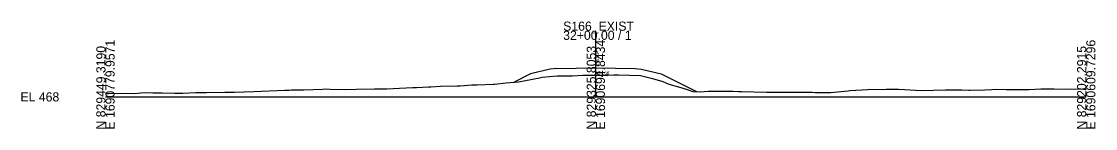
# Model space of a CAD drawing. Extents: x 1621104 to 1621433, y 1192880 to 1199414.
# Drawn here: x 1621104.2 to 1621432.7, y 1197379.5 to 1197412.3 of the extents above; entities that cross this region are included whole.
import ezdxf

# ---------------------------------------------------------------- set-up
doc = ezdxf.new("R2010")
doc.units = 0
for name, color, linetype in [('RD_GPK_XS_Cell', 7, 'Continuous'), ('RD_XS_EarthShd', 7, 'Continuous'), ('RD_XS_ExGround', 7, 'Continuous'), ('RD_XS_Pave', 7, 'Continuous'), ('RD_XS_TieSlope', 7, 'Continuous'), ('RD_XS_TX_Elev_EX', 7, 'Continuous'), ('RD_XS_TX_Elev_PR', 7, 'Continuous')]:
    doc.layers.add(name, color=color, linetype=linetype)

msp = doc.modelspace()

# ---------------------------------------------------------------- linework, layer by layer
at = {"layer": 'RD_GPK_XS_Cell'}
for p, q in [((1621279.86, 1197389.24), (1621279.86, 1197409.5)), ((1621129.86, 1197389.24), (1621279.86, 1197389.24)), ((1621279.86, 1197389.24), (1621429.86, 1197389.24))]:
    msp.add_line(p, q, dxfattribs=at)
at = {"layer": 'RD_XS_EarthShd'}
for p, q in [((1621267.86, 1197397.92), (1621265.86, 1197397.76)), ((1621291.86, 1197397.92), (1621293.86, 1197397.76))]:
    msp.add_line(p, q, dxfattribs=at)
at = {"layer": 'RD_XS_ExGround'}
msp.add_lwpolyline([(1621129.86, 1197390.23), (1621130.83, 1197390.29), (1621135.1, 1197390.33), (1621138.77, 1197390.28), (1621140.72, 1197390.47), (1621142.03, 1197390.55), (1621144.34, 1197390.45), (1621147.21, 1197390.44), (1621150.94, 1197390.4), (1621153.49, 1197390.43), (1621157.51, 1197390.56), (1621160.61, 1197390.58), (1621166.39, 1197390.65), (1621169.34, 1197390.68), (1621175.21, 1197390.89), (1621184.69, 1197391.27), (1621186.03, 1197391.3), (1621186.74, 1197391.35), (1621187.28, 1197391.37), (1621190.5, 1197391.36), (1621196.22, 1197391.63), (1621197.26, 1197391.68), (1621198.63, 1197391.61), (1621203.08, 1197391.52), (1621206.67, 1197391.59), (1621212.13, 1197391.68), (1621213.42, 1197391.71), (1621215.96, 1197391.71), (1621219.82, 1197391.96), (1621223.9, 1197392.08), (1621224.55, 1197392.1), (1621224.97, 1197392.14), (1621228.69, 1197392.33), (1621229.36, 1197392.35), (1621232.35, 1197392.48), (1621237.4, 1197392.65), (1621238.32, 1197392.66), (1621241.96, 1197392.89), (1621243.56, 1197392.98), (1621248.58, 1197393.13), (1621248.9, 1197393.15), (1621252.41, 1197393.5), (1621256.22, 1197393.88), (1621258.33, 1197394.21), (1621262.6, 1197395.04), (1621263.45, 1197395.23), (1621265.67, 1197395.44), (1621268.01, 1197395.73), (1621270.87, 1197395.66), (1621271.34, 1197395.65), (1621272.75, 1197395.7), (1621275.89, 1197395.85), (1621277.52, 1197395.88), (1621278.52, 1197395.94), (1621279.86, 1197395.92), (1621280.36, 1197395.91), (1621283.52, 1197395.94), (1621285.38, 1197395.99), (1621285.93, 1197395.98), (1621286.82, 1197395.96), (1621293.5, 1197395.76), (1621297.14, 1197394.85), (1621300.38, 1197393.93), (1621302.21, 1197393.17), (1621305.09, 1197392.36), (1621307.46, 1197391.62), (1621309.5, 1197390.91), (1621311.72, 1197390.82), (1621314.19, 1197391.01), (1621317.08, 1197391.02), (1621321.91, 1197390.96), (1621323.46, 1197390.91), (1621324.05, 1197390.91), (1621324.37, 1197390.91), (1621332.08, 1197390.67), (1621333.53, 1197390.68), (1621334.93, 1197390.66), (1621335.36, 1197390.66), (1621338.19, 1197390.66), (1621345.34, 1197390.71), (1621346.06, 1197390.69), (1621346.95, 1197390.62), (1621351.62, 1197390.56), (1621357.01, 1197391.12), (1621357.64, 1197391.18), (1621362.95, 1197391.54), (1621368.7, 1197391.65), (1621370, 1197391.64), (1621372.44, 1197391.6), (1621374.25, 1197391.54), (1621377.64, 1197391.31), (1621379.51, 1197391.22), (1621386.78, 1197391.41), (1621391.81, 1197391.44), (1621393.94, 1197391.32), (1621394.37, 1197391.29), (1621398.83, 1197391.42), (1621401.02, 1197391.53), (1621402.13, 1197391.57), (1621405.41, 1197391.48), (1621412.4, 1197391.55), (1621415.92, 1197391.66), (1621417.94, 1197391.71), (1621420, 1197391.73), (1621423.97, 1197391.64), (1621427.37, 1197391.69), (1621429.01, 1197391.57), (1621429.86, 1197391.56)], dxfattribs=at)
at = {"layer": 'RD_XS_Pave'}
for p, q in [((1621267.86, 1197397.92), (1621279.86, 1197398.16)), ((1621279.86, 1197398.16), (1621291.86, 1197397.92))]:
    msp.add_line(p, q, dxfattribs=at)
at = {"layer": 'RD_XS_TieSlope'}
for p, q in [((1621259.86, 1197396.26), (1621254.82, 1197393.74)), ((1621265.86, 1197397.76), (1621259.86, 1197396.26)), ((1621293.86, 1197397.76), (1621299.86, 1197396.26)), ((1621299.86, 1197396.26), (1621310.65, 1197390.87))]:
    msp.add_line(p, q, dxfattribs=at)

# ---------------------------------------------------------------- texts
at = {"layer": 'RD_GPK_XS_Cell'}
for s, p in [('32+00.00 / 1', (1621269.86, 1197406.7)), ('S166_EXIST', (1621269.86, 1197409.5)), ('EL 468', (1621103.86, 1197387.84))]:
    msp.add_text(s, height=2.8, dxfattribs=at).set_placement(p)
for s, p in [('E 1690779.9571', (1621132.66, 1197379.24)), ('E 1690694.8434', (1621282.66, 1197379.24)), ('E 1690609.7296', (1621432.66, 1197379.24)), ('N 829449.3190', (1621129.86, 1197379.24)), ('N 829325.8053', (1621279.86, 1197379.24)), ('N 829202.2915', (1621429.86, 1197379.24))]:
    msp.add_text(s, height=2.8, rotation=90, dxfattribs=at).set_placement(p)
at = {"layer": 'RD_XS_TX_Elev_EX'}
msp.add_text('474.68', height=1, dxfattribs=at).set_placement((1621279.76, 1197396.02))
at = {"layer": 'RD_XS_TX_Elev_PR'}
msp.add_text(' 476.93', height=1, rotation=90, dxfattribs=at).set_placement((1621280.86, 1197398.16))

doc.saveas('drawing.dxf')
